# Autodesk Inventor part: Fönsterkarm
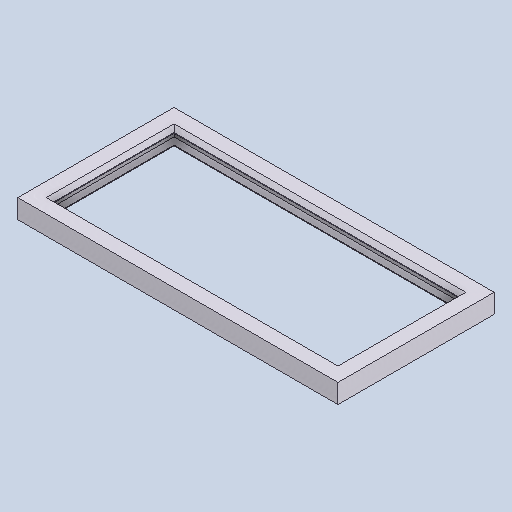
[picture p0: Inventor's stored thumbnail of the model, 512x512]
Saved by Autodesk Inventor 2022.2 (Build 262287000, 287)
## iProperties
Created: 2022-02
Part Number: Fönsterkarm
Material: Generic
Document SubType Name: Modeling
Designer: cl
Density: 1 g/cm^3
Appearance: Weld - Aluminum
Author: cl
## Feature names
1. Sweep1
## Parameters: BladBredd = 987.5 mm, Fönsterhöjd = 862 mm, Blad2 = 1012.5 mm, Blad3 = 0, Blad4 = 0, Blad5 = 1012.5 mm, Blad6 = 2025 mm, MGJ12Djup = 0, MGJ12Bredd = 0, MGJ2Djup = 0, MGJ2Bredd = 5012.5 mm, MGJ56Djup = 0, MGJ56Bredd = 0, MGJ23Djup = 48 mm, MGJ45Djup = 48 mm, GarageRegel5 = 0, GarageRegel6 = 0, Styrrulle2Djup = 0, FönsterhöjdStyrning = 862 mm, d3 = 15 mm, d4 = 45 deg, d5 = 2 mm, d7 = 54 mm, FönsterKarm = 54 mm, d9 = 15 mm, d10 = 45 deg, d11 = 2 mm, d13 = 90 deg, d14 = 902 mm, d17 = 0, d18 = 0
